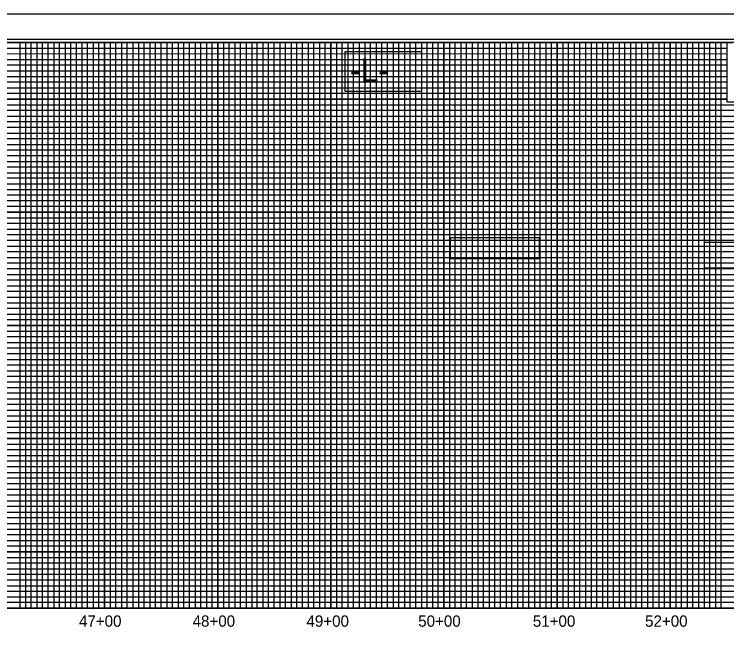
# Model space of a CAD drawing. Extents: x 1810963 to 1812908, y 722070 to 723170.
# Drawn here: x 1811601 to 1812230, y 722624 to 723170 of the extents above; entities that cross this region are included whole.
import ezdxf

# ---------------------------------------------------------------- set-up
doc = ezdxf.new("R2010")
doc.units = 0
for name, color, linetype in [('Exist Horizontal Alignment Tick Label', 7, 'Continuous'), ('Old_Level_11', 7, 'Continuous'), ('Old_Level_2', 7, 'Continuous'), ('Prop Conc 2ft 6in Curb and Gutter', 7, 'Continuous'), ('Prop RDY Traffic Signal CELL', 7, 'Continuous'), ('Prop Shade Heavy', 7, 'Continuous'), ('Prop Shade Light', 7, 'Continuous'), ('Scratch_Level_3', 7, 'Continuous'), ('Scratch_Level_5', 7, 'Continuous'), ('Sheet Block Title CELL', 7, 'Continuous'), ('Sheet North Arrow CELL', 7, 'Continuous'), ('Sheet Symbology CELL', 7, 'Continuous'), ('Sheet Title CELL', 7, 'Continuous')]:
    doc.layers.add(name, color=color, linetype=linetype)

msp = doc.modelspace()

# ---------------------------------------------------------------- linework, layer by layer
at = {"layer": 'Old_Level_11'}
msp.add_lwpolyline([(1810976.46, 722092.33), (1812642.96, 722092.33), (1812642.96, 723147.43), (1810976.46, 723147.43)], close=True, dxfattribs=at)
at = {"layer": 'Old_Level_2'}
for points in [[(1811893.13, 723136.89), (1811960.48, 723136.89), (1811960.48, 723101.51), (1811893.13, 723101.51)], [(1811986.13, 722972.52), (1812064.69, 722972.52), (1812064.69, 722953.81), (1811986.13, 722953.81)], [(1812210.84, 722968.52), (1812302.42, 722968.52), (1812302.42, 722945.34), (1812210.84, 722945.34)]]:
    msp.add_lwpolyline(points, close=True, dxfattribs=at)
at = {"layer": 'Prop Conc 2ft 6in Curb and Gutter'}
for p, q in [((1811630.46, 722644.88), (1811630.46, 723144.88)), ((1811680.46, 722644.88), (1811680.46, 723144.88)), ((1811730.46, 722644.88), (1811730.46, 723144.88)), ((1811780.46, 722644.88), (1811780.46, 723144.88)), ((1811830.46, 722644.88), (1811830.46, 723144.88)), ((1811880.46, 722644.88), (1811880.46, 723144.88)), ((1811930.46, 722644.88), (1811930.46, 723144.88)), ((1811980.46, 722644.88), (1811980.46, 723144.88)), ((1812030.46, 722644.88), (1812030.46, 723144.88)), ((1812080.46, 722644.88), (1812080.46, 723144.88)), ((1812130.46, 722644.88), (1812130.46, 723144.88)), ((1812180.46, 722644.88), (1812180.46, 723144.88)), ((1812230.42, 723094.88), (1811130.46, 723094.88)), ((1812430.41, 723044.88), (1811130.46, 723044.88)), ((1812430.46, 722994.88), (1811130.46, 722994.88)), ((1812630.46, 722944.88), (1811130.46, 722944.88)), ((1812630.46, 722894.88), (1811130.46, 722894.88)), ((1812630.46, 722844.88), (1811130.46, 722844.88)), ((1812630.46, 722794.88), (1811130.46, 722794.88)), ((1812630.46, 722744.88), (1811130.46, 722744.88)), ((1812630.46, 722694.88), (1811130.46, 722694.88))]:
    msp.add_line(p, q, dxfattribs=at)
at = {"layer": 'Prop RDY Traffic Signal CELL'}
msp.add_line((1812647.46, 723169.88), (1810963.46, 723169.88), dxfattribs=at)
at = {"layer": 'Prop Shade Heavy'}
for points in [[(1811580.46, 722644.88), (1811630.46, 722644.88), (1811630.46, 723144.88), (1811680.46, 723144.88), (1811680.46, 722644.88), (1811730.46, 722644.88), (1811730.46, 723144.88), (1811780.46, 723144.88), (1811780.46, 722644.88), (1811830.46, 722644.88), (1811830.46, 723144.88), (1811880.46, 723144.88), (1811880.46, 722644.88), (1811930.46, 722644.88), (1811930.46, 723144.88), (1811980.46, 723144.88), (1811980.46, 722644.88), (1812030.46, 722644.88), (1812030.46, 723144.88), (1812080.46, 723144.88), (1812080.46, 722644.88), (1812130.46, 722644.88), (1812130.46, 723144.88), (1812180.46, 723144.88), (1812180.46, 722644.88), (1812230.46, 722644.88)], [(1811130.46, 723094.88), (1812230.42, 723094.88)], [(1812430.46, 723044.88), (1811130.46, 723044.88), (1811130.46, 722994.88), (1812430.46, 722994.88)], [(1812630.46, 722944.88), (1811130.46, 722944.88), (1811130.46, 722894.88), (1812630.46, 722894.88)], [(1812630.46, 722844.88), (1811130.46, 722844.88), (1811130.46, 722794.88), (1812630.46, 722794.88)], [(1812630.46, 722744.88), (1811130.46, 722744.88), (1811130.46, 722744.88), (1811130.46, 722694.88), (1812630.46, 722694.88)]]:
    msp.add_lwpolyline(points, dxfattribs=at)
at = {"layer": 'Prop Shade Light'}
for p, q in [((1811555.46, 723144.88), (1811605.46, 723144.88)), ((1811605.46, 723144.88), (1811605.46, 722644.88)), ((1811655.46, 722644.88), (1811655.46, 723144.88)), ((1811655.46, 723144.88), (1811705.46, 723144.88)), ((1811705.46, 723144.88), (1811705.46, 722644.88)), ((1811755.46, 722644.88), (1811755.46, 723144.88)), ((1811755.46, 723144.88), (1811805.46, 723144.88)), ((1811805.46, 723144.88), (1811805.46, 722644.88)), ((1811855.46, 722644.88), (1811855.46, 723144.88)), ((1811855.46, 723144.88), (1811905.46, 723144.88)), ((1811905.46, 723144.88), (1811905.46, 722644.88)), ((1811955.46, 722644.88), (1811955.46, 723144.88)), ((1811955.46, 723144.88), (1812005.46, 723144.88)), ((1812005.46, 723144.88), (1812005.46, 722644.88)), ((1812055.46, 722644.88), (1812055.46, 723144.88)), ((1812055.46, 723144.88), (1812105.46, 723144.88)), ((1812105.46, 723144.88), (1812105.46, 722644.88)), ((1812155.46, 722644.88), (1812155.46, 723144.88)), ((1812155.46, 723144.88), (1812205.46, 723144.88)), ((1812205.46, 723144.88), (1812205.46, 722644.88)), ((1811130.46, 723119.88), (1812230.42, 723119.88)), ((1811605.46, 722644.88), (1811655.46, 722644.88)), ((1811705.46, 722644.88), (1811755.46, 722644.88)), ((1811755.46, 722644.88), (1811755.46, 722644.88)), ((1811805.46, 722644.88), (1811855.46, 722644.88)), ((1811905.46, 722644.88), (1811955.46, 722644.88)), ((1812005.46, 722644.88), (1812055.46, 722644.88)), ((1812105.46, 722644.88), (1812155.46, 722644.88)), ((1812205.46, 722644.88), (1812255.46, 722644.88))]:
    msp.add_line(p, q, dxfattribs=at)
for points in [[(1812430.46, 723069.88), (1811130.46, 723069.88), (1811130.46, 723019.88), (1812430.46, 723019.88)], [(1812630.46, 722969.88), (1811130.46, 722969.88), (1811130.46, 722919.88), (1812455.46, 722919.88)], [(1812630.46, 722869.88), (1811130.46, 722869.88), (1811130.46, 722819.88), (1812630.46, 722819.88)], [(1812630.46, 722769.88), (1811130.46, 722769.88), (1811130.46, 722719.88), (1812630.46, 722719.88)], [(1812630.46, 722669.88), (1811130.46, 722669.88)]]:
    msp.add_lwpolyline(points, dxfattribs=at)
at = {"layer": 'Scratch_Level_3'}
msp.add_lwpolyline([(1811180.46, 723144.88), (1812230.46, 723144.88), (1812230.46, 723092.45), (1812430.5, 723092.45), (1812430.41, 722983.83), (1812580.46, 722983.83), (1812580.46, 722644.88), (1811180.46, 722644.88)], close=True, dxfattribs=at)
at = {"layer": 'Scratch_Level_5'}
msp.add_lwpolyline([(1811180.46, 722983.83), (1811180.46, 722644.88), (1812580.46, 722644.88), (1812580.46, 722983.83)], dxfattribs=at)
at = {"layer": 'Sheet North Arrow CELL'}
msp.add_lwpolyline([(1810963.46, 722069.88), (1812647.46, 722069.88), (1812647.46, 723169.88), (1810963.46, 723169.88)], close=True, dxfattribs=at)
at = {"layer": 'Sheet Symbology CELL'}
msp.add_line((1811130.46, 722644.88), (1812630.46, 722644.88), dxfattribs=at)
msp.add_lwpolyline([(1812630.46, 723144.88), (1811130.46, 723144.88), (1811130.46, 722094.88), (1812630.46, 722094.88)], close=True, dxfattribs=at)
at = {"layer": 'Sheet Title CELL'}
for p, q in [((1811180.46, 723139.88), (1812230.42, 723139.88)), ((1812015.46, 722644.88), (1812015.46, 723144.88)), ((1812015.46, 723144.88), (1812020.46, 723144.88)), ((1812020.46, 723144.88), (1812020.46, 722644.88)), ((1812025.46, 722644.88), (1812025.46, 723144.88)), ((1812025.46, 723144.88), (1812035.46, 723144.88)), ((1812035.46, 723144.88), (1812035.46, 722644.88)), ((1812040.46, 722644.88), (1812040.46, 723144.88)), ((1812040.46, 723144.88), (1812045.46, 723144.88)), ((1812045.46, 723144.88), (1812045.46, 722644.88)), ((1812050.46, 722644.88), (1812050.46, 723144.88)), ((1812050.46, 723144.88), (1812060.46, 723144.88)), ((1812060.46, 723144.88), (1812060.46, 722644.88)), ((1812065.46, 722644.88), (1812065.46, 723144.88)), ((1812065.46, 723144.88), (1812070.46, 723144.88)), ((1812070.46, 723144.88), (1812070.46, 722644.88)), ((1812075.46, 722644.88), (1812075.46, 723144.88)), ((1812075.46, 723144.88), (1812085.46, 723144.88)), ((1812085.46, 723144.88), (1812085.46, 722644.88)), ((1812090.46, 722644.88), (1812090.46, 723144.88)), ((1812090.46, 723144.88), (1812095.46, 723144.88)), ((1812095.46, 723144.88), (1812095.46, 722644.88)), ((1812100.46, 722644.88), (1812100.46, 723144.88)), ((1812100.46, 723144.88), (1812110.46, 723144.88)), ((1812110.46, 723144.88), (1812110.46, 722644.88)), ((1812115.46, 722644.88), (1812115.46, 723144.88)), ((1812115.46, 723144.88), (1812120.46, 723144.88)), ((1812120.46, 723144.88), (1812120.46, 722644.88)), ((1812125.46, 722644.88), (1812125.46, 723144.88)), ((1812125.46, 723144.88), (1812135.46, 723144.88)), ((1812135.46, 723144.88), (1812135.46, 722644.88)), ((1812140.46, 722644.88), (1812140.46, 723144.88)), ((1812140.46, 723144.88), (1812145.46, 723144.88)), ((1812145.46, 723144.88), (1812145.46, 722644.88)), ((1812150.46, 722644.88), (1812150.46, 723144.88)), ((1812150.46, 723144.88), (1812160.46, 723144.88)), ((1812160.46, 723144.88), (1812160.46, 722644.88)), ((1812165.46, 722644.88), (1812165.46, 723144.88)), ((1812165.46, 723144.88), (1812170.46, 723144.88)), ((1812170.46, 723144.88), (1812170.46, 722644.88)), ((1812175.46, 722644.88), (1812175.46, 723144.88)), ((1812175.46, 723144.88), (1812185.46, 723144.88)), ((1812185.46, 723144.88), (1812185.46, 722644.88)), ((1812190.46, 722644.88), (1812190.46, 723144.88)), ((1812190.46, 723144.88), (1812195.46, 723144.88)), ((1812195.46, 723144.88), (1812195.46, 722644.88)), ((1812200.46, 722644.88), (1812200.46, 723144.88)), ((1812200.46, 723144.88), (1812210.46, 723144.88)), ((1812210.46, 723144.88), (1812210.46, 722644.88)), ((1812215.46, 722644.88), (1812215.46, 723144.88)), ((1812215.46, 723144.88), (1812220.46, 723144.88)), ((1812220.46, 723144.88), (1812220.46, 722644.88)), ((1812225.46, 722644.88), (1812225.46, 723144.88)), ((1812225.46, 723144.88), (1812235.46, 723144.88)), ((1812230.42, 723134.82), (1811180.46, 723134.53)), ((1811180.46, 723129.88), (1812230.42, 723129.88)), ((1812230.42, 723099.88), (1811180.46, 723099.88)), ((1811180.46, 723089.88), (1812430.46, 723089.88)), ((1812430.41, 723009.88), (1811180.46, 723009.88)), ((1812430.46, 723004.88), (1811180.46, 723004.88)), ((1812430.46, 722999.88), (1811180.46, 722999.88)), ((1811180.46, 722989.88), (1812430.46, 722989.88)), ((1812430.46, 722984.88), (1811180.46, 722984.88)), ((1811180.46, 722979.88), (1812580.46, 722979.88)), ((1812580.46, 722959.88), (1811180.46, 722959.88)), ((1811180.46, 722954.88), (1812580.46, 722954.88)), ((1812580.46, 722934.88), (1811180.46, 722934.88)), ((1811180.46, 722929.88), (1812580.46, 722929.88)), ((1812580.46, 722909.88), (1811180.46, 722909.88)), ((1811180.46, 722904.88), (1812580.46, 722904.88)), ((1812580.46, 722899.88), (1811180.46, 722899.88)), ((1811180.46, 722889.88), (1812580.46, 722889.88)), ((1812580.46, 722884.88), (1811180.46, 722884.88)), ((1811180.46, 722879.88), (1812580.46, 722879.88)), ((1812580.46, 722874.88), (1811180.46, 722874.88)), ((1811180.46, 722864.88), (1812580.46, 722864.88)), ((1812580.46, 722859.88), (1811180.46, 722859.88)), ((1811180.46, 722854.88), (1812580.46, 722854.88)), ((1812580.46, 722849.88), (1811180.46, 722849.88)), ((1811180.46, 722839.88), (1812580.46, 722839.88)), ((1812580.46, 722834.88), (1811180.46, 722834.88)), ((1811180.46, 722829.88), (1812580.46, 722829.88)), ((1812580.46, 722824.88), (1811180.46, 722824.88)), ((1811180.46, 722814.88), (1812580.46, 722814.88)), ((1812580.46, 722809.88), (1811180.46, 722809.88)), ((1811180.46, 722804.88), (1812580.46, 722804.88)), ((1812580.46, 722799.88), (1811180.46, 722799.88)), ((1811180.46, 722789.88), (1812580.46, 722789.88)), ((1812580.46, 722784.88), (1811180.46, 722784.88)), ((1811180.46, 722779.88), (1812580.46, 722779.88)), ((1812580.46, 722774.88), (1811180.46, 722774.88)), ((1811180.46, 722764.88), (1812580.46, 722764.88)), ((1812580.46, 722759.88), (1811180.46, 722759.88)), ((1812580.46, 722754.88), (1811180.46, 722754.88)), ((1812580.46, 722749.88), (1811180.46, 722749.88)), ((1811180.46, 722739.88), (1812580.46, 722739.88)), ((1812580.46, 722734.88), (1811180.46, 722734.88)), ((1811180.46, 722729.88), (1812580.46, 722729.88)), ((1812580.46, 722724.88), (1811180.46, 722724.88)), ((1811180.46, 722714.88), (1812580.46, 722714.88)), ((1812580.46, 722709.88), (1811180.46, 722709.88)), ((1811180.46, 722704.88), (1812580.46, 722704.88)), ((1812580.46, 722699.88), (1811180.46, 722699.88)), ((1811180.46, 722689.88), (1812580.46, 722689.88)), ((1812580.46, 722684.88), (1811180.46, 722684.88)), ((1811180.46, 722679.88), (1812580.46, 722679.88)), ((1812580.46, 722674.88), (1811180.46, 722674.88)), ((1811180.46, 722664.88), (1812580.46, 722664.88)), ((1812580.46, 722659.88), (1811180.46, 722659.88)), ((1811180.46, 722654.88), (1812580.46, 722654.88)), ((1812020.46, 722644.88), (1812025.46, 722644.88)), ((1812035.46, 722644.88), (1812040.46, 722644.88)), ((1812045.46, 722644.88), (1812050.46, 722644.88)), ((1812060.46, 722644.88), (1812065.46, 722644.88)), ((1812070.46, 722644.88), (1812075.46, 722644.88)), ((1812085.46, 722644.88), (1812090.46, 722644.88)), ((1812095.46, 722644.88), (1812100.46, 722644.88)), ((1812110.46, 722644.88), (1812115.46, 722644.88)), ((1812120.46, 722644.88), (1812125.46, 722644.88)), ((1812135.46, 722644.88), (1812140.46, 722644.88)), ((1812145.46, 722644.88), (1812150.46, 722644.88)), ((1812160.46, 722644.88), (1812165.46, 722644.88)), ((1812170.46, 722644.88), (1812175.46, 722644.88)), ((1812185.46, 722644.88), (1812190.46, 722644.88)), ((1812195.46, 722644.88), (1812200.46, 722644.88)), ((1812210.46, 722644.88), (1812215.46, 722644.88)), ((1812220.46, 722644.88), (1812225.46, 722644.88))]:
    msp.add_line(p, q, dxfattribs=at)
for points in [[(1811600.46, 723144.88), (1811610.46, 723144.88), (1811610.46, 722644.88), (1811615.46, 722644.88), (1811615.46, 723144.88), (1811620.46, 723144.88), (1811620.46, 722644.88), (1811625.46, 722644.88), (1811625.46, 723144.88), (1811635.46, 723144.88), (1811635.46, 722644.88), (1811640.46, 722644.88), (1811640.46, 723144.88), (1811645.46, 723144.88), (1811645.46, 722644.88), (1811650.46, 722644.88), (1811650.46, 723144.88), (1811660.46, 723144.88), (1811660.46, 722644.88), (1811665.46, 722644.88), (1811665.46, 723144.88), (1811670.46, 723144.88), (1811670.46, 722644.88), (1811675.46, 722644.88), (1811675.46, 723144.88), (1811685.46, 723144.88), (1811685.46, 722644.88), (1811690.46, 722644.88), (1811690.46, 723144.88), (1811695.46, 723144.88), (1811695.46, 722644.88), (1811700.46, 722644.88), (1811700.46, 723144.88), (1811710.46, 723144.88)], [(1811710.46, 723144.88), (1811710.46, 722644.88), (1811715.46, 722644.88), (1811715.46, 723144.88), (1811720.46, 723144.88), (1811720.46, 722644.88), (1811725.46, 722644.88), (1811725.46, 723144.88), (1811735.46, 723144.88), (1811735.46, 722644.88), (1811740.46, 722644.88), (1811740.46, 723144.88), (1811745.46, 723144.88), (1811745.46, 722644.88), (1811750.46, 722644.88), (1811750.46, 723144.88), (1811760.46, 723144.88), (1811760.46, 722644.88), (1811765.46, 722644.88), (1811765.46, 723144.88), (1811770.46, 723144.88), (1811770.46, 722644.88), (1811775.46, 722644.88), (1811775.46, 723144.88), (1811785.46, 723144.88), (1811785.46, 722644.88), (1811790.46, 722644.88), (1811790.46, 723144.88), (1811795.46, 723144.88), (1811795.46, 722644.88), (1811800.46, 722644.88), (1811800.46, 723144.88), (1811810.46, 723144.88), (1811810.46, 722644.88), (1811815.46, 722644.88), (1811815.46, 723144.88), (1811820.46, 723144.88), (1811820.46, 722644.88), (1811825.46, 722644.88), (1811825.46, 723144.88), (1811835.46, 723144.88), (1811835.46, 722644.88), (1811835.46, 722644.88), (1811840.46, 722644.88), (1811840.46, 723144.88), (1811845.46, 723144.88), (1811845.46, 722644.88), (1811850.46, 722644.88), (1811850.46, 723144.88), (1811860.46, 723144.88), (1811860.46, 722644.88), (1811865.46, 722644.88), (1811865.46, 723144.88), (1811870.46, 723144.88), (1811870.46, 722644.88), (1811875.46, 722644.88), (1811875.46, 723144.88), (1811885.46, 723144.88), (1811885.46, 722644.88), (1811890.46, 722644.88), (1811890.46, 723144.88), (1811895.46, 723144.88), (1811895.46, 722644.88), (1811900.46, 722644.88), (1811900.46, 723144.88), (1811910.46, 723144.88), (1811910.46, 722644.88), (1811915.46, 722644.88), (1811915.46, 723144.88), (1811920.46, 723144.88), (1811920.46, 722644.88), (1811925.46, 722644.88), (1811925.46, 723144.88), (1811935.46, 723144.88), (1811935.46, 722644.88), (1811940.46, 722644.88), (1811940.46, 723144.88), (1811945.46, 723144.88), (1811945.46, 722644.88), (1811950.46, 722644.88), (1811950.46, 723144.88), (1811960.46, 723144.88), (1811960.46, 722644.88), (1811965.46, 722644.88), (1811965.46, 723144.88), (1811970.46, 723144.88), (1811970.46, 722644.88), (1811975.46, 722644.88), (1811975.46, 723144.88), (1811985.46, 723144.88), (1811985.46, 722644.88), (1811990.16, 722645.43), (1811990.46, 722644.88), (1811990.46, 723144.88), (1811995.46, 723144.88), (1811995.46, 722644.88), (1812000.46, 722644.88), (1812000.46, 723144.88), (1812010.46, 723144.88), (1812010.46, 722644.88), (1812015.46, 722644.88)], [(1812230.42, 723124.88), (1811180.46, 723124.88), (1811180.46, 723114.88), (1812230.42, 723114.88)], [(1812230.42, 723109.88), (1811180.46, 723109.88), (1811180.46, 723104.88), (1812230.42, 723104.88)], [(1812430.46, 723084.88), (1811180.46, 723084.88), (1811180.46, 723079.88), (1812430.46, 723079.88)], [(1812430.46, 723074.88), (1811180.46, 723074.88), (1811180.46, 723064.88), (1812430.46, 723064.88)], [(1812430.46, 723059.88), (1811180.46, 723059.88), (1811180.46, 723054.88), (1812430.46, 723054.88)], [(1812430.46, 723049.88), (1811180.46, 723049.88), (1811180.46, 723039.88), (1812430.46, 723039.88)], [(1812430.46, 723034.78), (1811180.56, 723034.78), (1811180.56, 723029.88), (1812430.46, 723029.88)], [(1812430.46, 723024.88), (1811180.46, 723024.88), (1811180.46, 723014.88), (1812430.46, 723014.88)], [(1812580.46, 722974.88), (1811180.46, 722974.88), (1811180.46, 722964.88), (1812580.46, 722964.88)], [(1812580.46, 722949.88), (1811180.46, 722949.88), (1811180.46, 722939.88), (1812580.46, 722939.88)], [(1812580.46, 722924.88), (1811180.46, 722924.88), (1811180.46, 722914.88), (1812580.46, 722914.88)], [(1812580.46, 722649.88), (1811180.46, 722649.88)]]:
    msp.add_lwpolyline(points, dxfattribs=at)

# ---------------------------------------------------------------- texts
at = {"layer": 'Exist Horizontal Alignment Tick Label'}
msp.add_text('-L-', height=21, rotation=360, dxfattribs=at).set_placement((1811897.42, 723109.94))
at = {"layer": 'Sheet Block Title CELL'}
for s, p in [('47+00', (1811657.81, 722628.6)), ('48+00', (1811758.26, 722628.6)), ('49+00', (1811858.9, 722628.6)), ('50+00', (1811957.68, 722628.6)), ('51+00', (1812059.01, 722628.6)), ('52+00', (1812158.26, 722628.6))]:
    msp.add_text(s, height=10, dxfattribs=at).set_placement(p)

doc.saveas('drawing.dxf')
